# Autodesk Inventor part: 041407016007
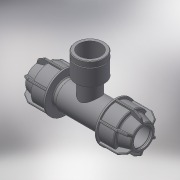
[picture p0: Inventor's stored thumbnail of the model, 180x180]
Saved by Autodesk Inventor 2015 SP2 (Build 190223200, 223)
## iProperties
Created: 2017-08
Part Number: 041407016007
Material: Generic
Description: PLASSON IRRIFIT TEE FEMALE ADAPTOR 16-3/4"-16
Document SubType Name: Modeling
Designer: KIM
Density: 1 g/cm^3
Appearance: Default
Author: KIM
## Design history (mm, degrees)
derived "041407.ipt"
feature "Solid1::041407.ipt"
feature "Solid2::041407.ipt"
tag "TaggingFeature1"
body "Solid1"
other parameters: "d1" = 16, "d2" = 25, "d4" = 15 deg, "d5" = 23.75, "d6" = 9.5, "d10" = 34, "d16" = 16.32, "d17" = 1.25, "d22" = 20.8, "d24" = 1.25, "d25" = 30.6, "d26" = 25.5, "d27" = 1.25, "d28" = 135 deg, "d29" = 0.75, "d31" = 0.8, "d46" = 150 deg, "d49" = 1.7, "d50" = 0, "d58" = 0.48, "d61" = 360 deg, "d63" = 14.4, "d64" = 45, "d80" = 22.88, "d81" = 0.16, "d94" = 44, "d96" = 31.3521, "d108" = 0.48, "d113" = 16.8819, "d115" = 20.4, "d117" = 21.7053, "d118" = 2.5, "d119" = 17, "d120" = 24.117, "d121" = 0.48234, "d122" = 5.1, "d123" = 2.5, "d128" = 31.3521, "d130" = 0, "d132" = 0, "d_" = 16, "G_" = 24.117, "E_" = 34, "l_" = 25, "l_1" = 17, "A_" = 44
